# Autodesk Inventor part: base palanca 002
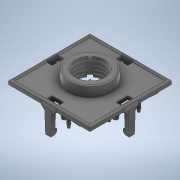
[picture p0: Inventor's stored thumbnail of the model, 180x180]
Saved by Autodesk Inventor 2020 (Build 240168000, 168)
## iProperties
Created: 2022-02
Part Number: base palanca 002
Material: Plástico ABS
Document SubType Name: Modeling
Designer: Eresthor
Density: 1.06 g/cm^3
Appearance: Suave - Negro
Author: Eresthor
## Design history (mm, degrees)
sketch "Boceto1"
  geometry: L1 (-13, 0)-(-18, 0); L2 (-18, 0)-(-18, 11); L3 (0, 12)-(0, 0); L4 (-17, 12)-(-13, 12); L5 (-13, 12)-(-13, 9.25); L6 (-13, 8.25)-(-13, 5.5); L7 (-13, 4.5)-(-13, 2.75); L8 (-13, 1.75)-(-13, 0); A1 r 0.5 centre (-13, 8.75) between (-13, 8.25) and (-13, 9.25); A2 r 0.5 centre (-13, 5) between (-13, 4.5) and (-13, 5.5); A3 r 0.5 centre (-13, 2.25) between (-13, 1.75) and (-13, 2.75); A4 r 1 centre (-17, 11) between (-17, 12) and (-18, 11)
  constraints: 16 end point, 8 point on circle, 4 centre point, 4 perpendicular, 2 horizontal, 2 tangent, 1 vertical
revolve "Revolución1" sketch "Boceto1" stored, may be unused: angle "d11" = 90 deg
sketch "Boceto2"
  geometry: L1 (-6, -36)-(6, -36); L2 (36, -6)-(36, 6); L3 (6, 36)-(-6, 36); L4 (-36, 6)-(-36, -6); L5 (-35, -6)-(-36, -6); L6 (-35, 6)-(-36, 6); L7 (36, -6)-(35, -6); L8 (36, 6)-(35, 6); L9 (6, -36)-(6, -35); L10 (-6, -36)-(-6, -35); L11 (35, 35)-(35, 6); L12 (35, -6)-(35, -35); L13 (-35, 35)-(-6, 35); L14 (6, 35)-(35, 35); L15 (35, -35)-(6, -35); L16 (-6, -35)-(-35, -35); L17 (-35, -35)-(-35, -6); L18 (-35, 6)-(-35, 35); L19 (-6, 35)-(-6, 36); L20 (6, 35)-(6, 36); C1 r 18 at (0, 0)
  constraints: 40 end point, 10 parallel, 5 perpendicular, 2 horizontal, 1 centre point
  dimensions: "d12" = 70 distance of L13.start L11.start; "d13" = 70 distance of L16.end L13.start
extrude "Extrusión1" join sketch "Boceto2" distance "d19" = 3; taper "d20" = 0 deg
feature "Cara para el ángulo de desmoldeo1" dims angle "d21" = 18.43 deg
feature "Cara para el ángulo de desmoldeo2" dims angle "d22" = 45 deg
feature "Cara para el ángulo de desmoldeo3" dims angle "d23" = 45 deg
feature "Cara para el ángulo de desmoldeo4" dims angle "d24" = 45 deg
feature "Cara para el ángulo de desmoldeo5" dims angle "d25" = 45 deg
sketch "Boceto3"
  geometry: L1 (35, -35)-(35, -6) reference; L2 (-35, 35)-(35, 35); L3 (35, 35)-(35, -35); L4 (35, -35)-(-35, -35); L5 (-35, -35)-(-35, 35); L6 (-35, 35)-(35, -35); L7 (35, 35)-(-35, -35); L8 (-32, 32)-(32, 32); L9 (32, 32)-(32, -32); L10 (32, -32)-(-32, -32); L11 (-32, -32)-(-32, 32); L12 (-32, 32)-(32, -32); L13 (32, 32)-(-32, -32); 2 further points
  constraints: 24 end point, 4 midpoint, 4 parallel, 2 horizontal, 2 perpendicular
  dimensions: "d26" = 64 distance of L9.end L10.end; "d27" = 64 distance of L8.end L9.end
extrude "Extrusión2" join sketch "Boceto3" distance "d28" = 1; taper "d29" = 0 deg
fillet "Empalme1" dims "d30" = 1
fillet "Empalme2" dims "d31" = 1.5
sketch "Boceto5"
  geometry: L1 (-7.778, 7.778)-(-8.072, 10.19); L2 (-7.778, 7.778)-(-10.19, 8.072); L3 (7.778, -7.778)-(8.072, -10.19); L4 (7.778, -7.778)-(10.19, -8.072); A1 r 13 centre (0, 0) between (-8.072, 10.19) and (-10.19, 8.072) reference; A2 r 13 centre (0, 0) between (-8.072, 10.19) and (-10.19, 8.072); A3 r 13 centre (0, 0) between (8.072, -10.19) and (10.19, -8.072)
  constraints: 8 end point, 5 point on circle, 2 centre point
extrude "Extrusión4" join sketch "Boceto5" distance "d46" = 4; taper "d47" = 0 deg
sketch "Boceto6"
  geometry: L1 (68.5, 68.5)-(1.5, 68.5) reference; L2 (41, 0)-(29, 0) reference; L3 (69.914, 41.086)-(69.914, 28.914) reference; L4 (0, 29)-(0, 41) reference; L5 (40, 67.5)-(30, 67.5); L6 (2.5, 40)-(2.5, 30); L7 (30, 2.5)-(40, 2.5); L8 (67.5, 30)-(67.5, 40); L9 (40, 7.5)-(30, 7.5); L10 (7.5, 30)-(7.5, 40); L11 (30, 62.5)-(40, 62.5); L12 (62.5, 40)-(62.5, 30); L13 (40, 7.5)-(40, 2.5); L14 (30, 7.5)-(30, 2.5); L15 (7.5, 30)-(2.5, 30); L16 (7.5, 40)-(2.5, 40); L17 (30, 67.5)-(30, 62.5); L18 (40, 67.5)-(40, 62.5); L19 (67.5, 40)-(62.5, 40); L20 (67.5, 30)-(62.5, 30); 1 further point
  constraints: 32 end point, 4 parallel, 2 perpendicular, 1 horizontal
extrude "Extrusión5" cut sketch "Boceto6" distance "d55" = 4; taper "d56" = 0 deg
sketch "Boceto7"
  geometry: L1 (42, 0)-(70, 0) reference; L2 (70, 0)-(70, 28) reference; L3 (68.531, 9.872)-(67.391, 25.831); L4 (40.603, 7.877)-(39.61, 21.781); L5 (68.531, 9.872)-(40.603, 7.877); L6 (67.391, 25.831)-(43.847, 24.15); L7 (60.128, 68.531)-(62.123, 40.603); L8 (60.128, 68.531)-(44.169, 67.391); L9 (44.169, 67.391)-(45.85, 43.847); L10 (62.123, 40.603)-(48.219, 39.61); L11 (1.469, 60.128)-(29.397, 62.123); L12 (1.469, 60.128)-(2.609, 44.169); L13 (2.609, 44.169)-(26.153, 45.85); L14 (29.397, 62.123)-(30.39, 48.219); L15 (9.872, 1.469)-(7.877, 29.397); L16 (9.872, 1.469)-(25.831, 2.609); L17 (25.831, 2.609)-(24.15, 26.153); L18 (7.877, 29.397)-(21.781, 30.39); C1 r 11 at (35, 35); C2 r 1.5 at (64.196, 23.176); C3 r 1.5 at (43.798, 10.534); C4 r 1.5 at (59.466, 43.798); C5 r 1.5 at (46.824, 64.196); C6 r 1.5 at (26.202, 59.466); C7 r 1.5 at (5.804, 46.824); C8 r 1.5 at (10.534, 26.202); C9 r 1.5 at (23.176, 5.804); A1 r 14 centre (35, 35) between (24.15, 26.153) and (39.61, 21.781); A2 r 14 centre (35, 35) between (26.153, 45.85) and (21.781, 30.39); A3 r 14 centre (35, 35) between (43.847, 24.15) and (48.219, 39.61); A4 r 14 centre (35, 35) between (45.85, 43.847) and (30.39, 48.219); 2 further points
  constraints: 32 end point, 13 centre point, 8 point on circle, 1 parallel, 53 other
  dimensions: "d118" = 360 deg dimension on point (35, 35) L3.start (derived)
extrude "Extrusión6" join sketch "Boceto7" distance "d120" = 2; taper "d121" = 0 deg
sketch "Boceto8"
  geometry: L1 (45.855, 43.026)-(44.063, 41.234); L2 (28.766, 25.937)-(26.974, 24.145); L3 (43.026, 45.855)-(41.234, 44.063); L4 (25.937, 28.766)-(24.145, 26.974); A1 r 11 centre (35, 35) between (44.063, 41.234) and (41.234, 44.063); A2 r 11 centre (35, 35) between (25.937, 28.766) and (28.766, 25.937); A3 r 13.5 centre (35, 35) between (45.855, 43.026) and (43.026, 45.855); A4 r 13.5 centre (35, 35) between (24.145, 26.974) and (26.974, 24.145); 1 further point
  constraints: 8 end point, 8 point on circle, 4 centre point, 2 coincident
extrude "Extrusión7" cut sketch "Boceto8" distance "d126" = 10; taper "d127" = 0 deg
sketch "Boceto9"
  geometry: L1 (67.5, -12)-(62.5, -12) reference; L2 (64.58, -12)-(67.619, -12); L3 (67, -2)-(62.5, -2) reference; L4 (64.58, -2)-(67.619, -2); L5 (40, -39)-(40, -34.5) reference; L6 (40, -36.58)-(40, -39.619); L7 (30, -34.5)-(30, -39) reference; L8 (30, -36.58)-(30, -39.619); L9 (3, -12)-(7.5, -12) reference; L10 (5.42, -12)-(2.381, -12); L11 (2.5, -2)-(7.5, -2) reference; L12 (5.42, -2)-(2.381, -2); L13 (30, 20.5)-(30, 25.5) reference; L14 (30, 22.58)-(30, 25.619); L15 (40, 25.5)-(40, 20.5) reference; L16 (40, 22.58)-(40, 25.619); L17 (68.5, -40.5)-(70, -42) reference; L18 (28, 28)-(0, 28) reference; L19 (28.833, -42)-(0, -42) reference; L20 (70, 28)-(70, -0.833) reference; L21 (25.831, -39.391)-(24.15, -15.847) reference; L22 (25.552, -35.473)-(25.781, -38.686); L23 (7.877, -12.603)-(9.872, -40.531) reference; L24 (9.453, -34.668)-(9.17, -30.708); L25 (8.921, -27.221)-(8.479, -21.022); L26 (6.527, 2.448)-(3.314, 2.219); L27 (29.397, 20.123)-(1.469, 18.128) reference; L28 (14.779, 19.079)-(20.978, 19.521); L29 (3.887, -40.234)-(9.453, -34.668); L30 (10.629, -29.25)-(1.766, -38.113); L31 (14.874, 15.247)-(4.241, 25.88); L32 (6.527, 2.448)-(3.314, 2.219); L33 (2.609, 2.169)-(26.153, 3.85) reference; L34 (26.153, 3.85)-(22.303, 3.575); L35 (7.332, 18.547)-(11.292, 18.83); L36 (2.12, 23.759)-(12.753, 13.126); L37 (22.303, 3.575)-(24.097, 1.782); L38 (44.395, 21.491)-(44.219, 24.686); L39 (45.85, 1.847)-(44.169, 25.391) reference; L40 (45.85, 1.847)-(45.575, 5.697); L41 (62.123, -1.397)-(60.128, 26.531) reference; L42 (60.83, 16.708)-(60.547, 20.668); L43 (61.079, 13.221)-(61.521, 7.022); L44 (45.575, 5.697)-(43.782, 3.903); L45 (66.113, 26.234)-(60.547, 20.668); L46 (57.247, 13.126)-(59.371, 15.25); L47 (60.83, 16.708)-(68.234, 24.113); L48 (40.603, -34.123)-(68.531, -32.128) reference; L49 (62.668, -32.547)-(58.708, -32.83); L50 (55.221, -33.079)-(49.022, -33.521); L51 (67.391, -16.169)-(43.847, -17.85) reference; L52 (66.686, -16.219)-(63.473, -16.448); L53 (47.697, -17.575)-(43.847, -17.85); L54 (46.729, -20.85)-(47.529, -21.65); L55 (58.708, -32.83)-(65.759, -39.88); L56 (67.88, -37.759)-(62.668, -32.547); L57 (59.371, -29.25)-(57.247, -27.126); L58 (47.697, -17.575)-(45.903, -15.782); C1 r 1.5 at (64.196, -18.824) reference; A1 r 1.5 centre (67.173, 25.173) between (68.234, 24.113) and (66.113, 26.234); A2 r 1.5 centre (2.827, -39.173) between (1.766, -38.113) and (3.887, -40.234); A3 r 14 centre (35, -7) between (26.153, 3.85) and (21.781, -11.61) reference; A4 r 14 centre (35, -7) between (45.903, -15.782) and (43.782, 3.903); A5 r 30 centre (35, -7) between (25.552, -35.473) and (30, -36.58); A6 r 33 centre (35, -7) between (2.381, -12) and (12.75, -31.371); A7 r 33 centre (35, -7) between (25.781, -38.686) and (30, -39.619); A8 r 30 centre (35, -7) between (5.42, -12) and (8.479, -21.022); A9 r 30 centre (35, -7) between (12.753, -27.126) and (14.874, -29.247); A10 r 1.5 centre (66.82, -38.82) between (65.759, -39.88) and (67.88, -37.759); A11 r 1.5 centre (3.18, 24.82) between (4.241, 25.88) and (2.12, 23.759); A12 r 30 centre (35, -7) between (30, 22.58) and (12.753, 13.126); A13 r 30 centre (35, -7) between (6.527, 2.448) and (5.42, -2); A14 r 33 centre (35, -7) between (30, 25.619) and (10.629, 15.25); A15 r 33 centre (35, -7) between (3.314, 2.219) and (2.381, -2); A16 r 30 centre (35, -7) between (44.448, 21.473) and (40, 22.58); A17 r 33 centre (35, -7) between (44.219, 24.686) and (40, 25.619); A18 r 33 centre (35, -7) between (67.619, -2) and (61.079, 13.221); A19 r 33 centre (35, -7) between (59.371, 15.25) and (57.25, 17.371); A20 r 30 centre (35, -7) between (64.58, -2) and (61.521, 7.022); A21 r 30 centre (35, -7) between (40, -36.58) and (49.022, -33.521); A22 r 33 centre (35, -7) between (40, -39.619) and (55.221, -33.079); A23 r 33 centre (35, -7) between (66.686, -16.219) and (67.619, -12); A24 r 30 centre (35, -7) between (55.126, -29.247) and (57.247, -27.126); A25 r 30 centre (35, -7) between (63.473, -16.448) and (64.58, -12); 14 further points
  constraints: 76 end point, 55 point on circle, 45 point on line, 28 tangent, 25 parallel, 24 centre point, 5 collinear, 1 coincident
extrude "Extrusión8" join sketch "Boceto9" distance "d139" = 1.5; taper "d140" = 0 deg
sketch "Boceto10"
  geometry: C1 r 3.5 at (-27.5, -17); C2 r 3.5 at (-5.5, 5); C3 r 3.5 at (-27.5, 27); C4 r 3.5 at (-49.5, 5); C5 r 1 at (-5.5, 5); C6 r 1 at (-49.5, 5); C7 r 1 at (-27.5, 27); C8 r 1 at (-27.5, -17); C9 r 22 at (-27.5, 5); A1 r 11 centre (-27.5, 5) between (-33.734, -4.063) and (-18.437, 11.234) reference; 2 further points
  constraints: 9 centre point, 5 coincident, 9 other
  dimensions: "d145" = 360 deg dimension on point (-27.5, 5) C1.centre (derived); "d147" = 2 diameter of C5; "d148" = 2 diameter of C6; "d149" = 2 diameter of C7; "d150" = 2 diameter of C8; "d356" = 44 diameter of C9
extrude "Extrusión9" join sketch "Boceto10" distance "d151" = 14; taper "d152" = 0 deg
chamfer "Chaflán1" distance "d153" = 1.5; stored, may be unused: second distance "d154" = 2, angle "d155" = 80 deg
chamfer "Chaflán2" distance "d156" = 1.5; stored, may be unused: second distance "d157" = 2, angle "d158" = 80 deg
chamfer "Chaflán3" distance "d159" = 1.5; stored, may be unused: second distance "d160" = 2, angle "d161" = 80 deg
chamfer "Chaflán4" distance "d162" = 1.5; stored, may be unused: second distance "d163" = 2, angle "d164" = 80 deg
sketch "Boceto11"
  geometry: L1 (29, -43)-(41, -43) reference; L2 (40, -39.5)-(30, -39.5) reference; L3 (38, -39.5)-(32, -39.5); L4 (32, -39.5)-(32, -43); L5 (32, -43)-(38, -43); L6 (38, -43)-(38, -39.5); L7 (71, -10)-(71, -4); L8 (67.5, -10)-(71, -10); L9 (67.5, -4)-(67.5, -10); L10 (71, -4)-(67.5, -4); L11 (38, 29)-(32, 29); L12 (38, 25.5)-(38, 29); L13 (32, 25.5)-(38, 25.5); L14 (32, 29)-(32, 25.5); L15 (-1, -4)-(-1, -10); L16 (2.5, -4)-(-1, -4); L17 (2.5, -10)-(2.5, -4); L18 (-1, -10)-(2.5, -10); 5 further points
  constraints: 32 end point, 2 parallel, 1 horizontal, 1 perpendicular, 33 other
  dimensions: "d165" = 6 distance of L5.end L4.end; "d166" = 3.5 distance of L4.end L3.end; "d169" = 360 deg dimension on point (35, -7) L4.end (derived)
extrude "Extrusión10" join sketch "Boceto11" distance "d171" = 16; taper "d172" = 0 deg
sketch "Boceto12"
  geometry: L1 (32, -43)-(38, -43) reference; L2 (38, -43)-(32, -43); L3 (32, -43)-(32, -38); L4 (32, -38)-(38, -38); L5 (38, -38)-(38, -43); L6 (71, -10)-(66, -10); L7 (71, -4)-(71, -10); L8 (66, -4)-(71, -4); L9 (66, -10)-(66, -4); L10 (38, 29)-(38, 24); L11 (32, 29)-(38, 29); L12 (32, 24)-(32, 29); L13 (38, 24)-(32, 24); L14 (-1, -4)-(4, -4); L15 (-1, -10)-(-1, -4); L16 (4, -10)-(-1, -10); L17 (4, -4)-(4, -10); 2 further points
  constraints: 32 end point, 2 parallel, 1 horizontal, 1 perpendicular, 33 other
  dimensions: "d173" = 6 distance of L3.end L4.end; "d174" = 5 distance of L2.end L3.end; "d177" = 360 deg dimension on point (35, -7) L2.end (derived)
extrude "Extrusión11" join sketch "Boceto12" distance "d179" = 4; taper "d180" = 0 deg
chamfer "Chaflán5" distance "d181" = 1.5; stored, may be unused: second distance "d182" = 2, angle "d183" = 80 deg
feature "Cara para el ángulo de desmoldeo6" dims angle "d184" = 2 deg
feature "Cara para el ángulo de desmoldeo7" dims angle "d185" = 2 deg
feature "Cara para el ángulo de desmoldeo8" dims angle "d186" = 2 deg
feature "Cara para el ángulo de desmoldeo9" dims angle "d187" = 2 deg
node "Plano de trabajo1"
node "Plano de trabajo2"
node "Plano de trabajo3"
node "Plano de trabajo4"
sketch "Boceto13"
  geometry: L1 (7.61, 0)-(-5.782, 0) reference; L2 (6, 0)-(5.302, -20) reference; L3 (5.895, -2.998)-(9, 0); L4 (9.234, 0)-(-8, 0) reference; L5 (-2.98, 0)-(0.105, -2.999); L6 (0, 0)-(0.698, -20) reference; 2 further points
  constraints: 4 end point, 4 point on line
feature "Nervio1" sketch "Boceto13" dims "d194" = 1, "d195" = 3, "d196" = 0, "d197" = 0, "d198" = 1, "d199" = 1
sketch "Boceto14"
  geometry: L1 (0, 0)-(0.698, -20) reference; L2 (0.105, -2.998)-(-3, 0); L3 (-2, 0)-(-6.219, 0) reference; 1 further point
  constraints: 2 end point, 2 point on line
feature "Nervio2" sketch "Boceto14" dims "d201" = 1, "d202" = 3, "d203" = 0, "d204" = 0, "d205" = 1, "d206" = 1
sketch "Boceto15"
  geometry: L1 (6, 0)-(5.441, -16) reference; L2 (0, 0)-(0.559, -16) reference; L3 (9, 0)-(9, 3) reference; L4 (9, 0)-(5.895, -2.998); L5 (14, 0)-(-3.234, 0) reference; 2 further points
  constraints: 2 end point, 1 point on line
feature "Nervio3" sketch "Boceto15" dims "d209" = 1, "d210" = 3, "d211" = 0, "d212" = 0, "d213" = 1, "d214" = 1
sketch "Boceto16"
  geometry: 1 further point
sketch "Boceto17"
  geometry: L1 (0, 0)-(0.559, -16) reference; L2 (14, 0)-(-3.234, 0) reference; L3 (-3, 0)-(0.105, -2.998); 2 further points
  constraints: 2 end point, 2 point on line
feature "Nervio4" sketch "Boceto17" dims "d216" = 1, "d217" = 3, "d218" = 0, "d219" = 0, "d220" = 1, "d221" = 1
sketch "Boceto18"
  geometry: L1 (6, 0)-(5.302, -20) reference; L2 (10.669, 0)-(-10, 0) reference; L3 (9, 0)-(5.895, -2.998); 2 further points
  constraints: 2 end point, 2 point on line
feature "Nervio5" sketch "Boceto18" dims "d223" = 1, "d224" = 3, "d225" = 0, "d226" = 0, "d227" = 1, "d228" = 1
sketch "Boceto19"
  geometry: L1 (-2, 0)-(0, 0) reference; L2 (-3, 0)-(0.105, -2.998); L3 (0, 0)-(0.698, -20) reference; 1 further point
  constraints: 2 end point, 1 point on line
feature "Nervio6" sketch "Boceto19" dims "d230" = 1, "d231" = 3, "d232" = 0, "d233" = 0, "d234" = 1, "d235" = 1
sketch "Boceto20"
  geometry: L1 (6, 0)-(5.441, -16) reference; L2 (10.669, 0)-(-10, 0) reference; L3 (9, 0)-(5.895, -2.998); 2 further points
  constraints: 2 end point, 2 point on line
feature "Nervio7" sketch "Boceto20" dims "d237" = 1, "d238" = 3, "d239" = 0, "d240" = 0, "d241" = 1, "d242" = 1
sketch "Boceto21"
  geometry: L1 (0, 0)-(0.559, -16) reference; L2 (-11.022, 0)-(-2.603, 0) reference; L3 (-3, 0)-(0.105, -2.998); 1 further point
  constraints: 2 end point, 2 point on line
feature "Nervio8" sketch "Boceto21" dims "d244" = 1, "d245" = 3, "d246" = 0, "d247" = 0, "d248" = 1, "d249" = 1
sketch "Boceto22"
  geometry: C1 r 1.5 at (0, 0) reference; C2 r 1.5 at (0, 0); C3 r 1.5 at (-20.399, -12.642) reference; C4 r 1.5 at (-20.399, -12.642); C5 r 1.5 at (-41.021, -17.372) reference; C6 r 1.5 at (-41.021, -17.372); C7 r 1.5 at (-53.663, 3.027) reference; C8 r 1.5 at (-53.663, 3.027); C9 r 1.5 at (-58.393, 23.649) reference; C10 r 1.5 at (-58.393, 23.649); C11 r 1.5 at (-37.994, 36.291) reference; C12 r 1.5 at (-37.994, 36.291); C13 r 1.5 at (-17.372, 41.021) reference; C14 r 1.5 at (-17.372, 41.021); C15 r 1.5 at (-4.73, 20.622) reference; C16 r 1.5 at (-4.73, 20.622); 1 further point
  constraints: 8 centre point, 8 coincident
extrude "Extrusión12" join sketch "Boceto22" distance "d250" = 2; taper "d251" = 0 deg
sketch "Boceto25"
  geometry: C1 r 1.5 at (4.924, 46.84); C2 r 1.5 at (27.082, 59.451); C3 r 1.5 at (10.549, 27.082); C4 r 1.5 at (23.16, 4.924); C5 r 1.5 at (42.918, 10.549); C6 r 1.5 at (65.076, 23.16); C7 r 1.5 at (59.451, 42.918); C8 r 1.5 at (46.84, 65.076); 2 further points
  constraints: 8 centre point, 17 other
  dimensions: "d328" = 360 deg dimension on point (35, 35) C2.centre (derived)
extrude "Extrusión15" join sketch "Boceto25" distance "d330" = 9; taper "d331" = 0 deg
chamfer "Chaflán22" distance "d332" = 0.5; stored, may be unused: second distance "d333" = 3, angle "d334" = 45 deg
chamfer "Chaflán23" distance "d335" = 0.5; stored, may be unused: second distance "d336" = 3, angle "d337" = 45 deg
chamfer "Chaflán24" distance "d338" = 0.5; stored, may be unused: second distance "d339" = 3, angle "d340" = 45 deg
chamfer "Chaflán25" distance "d341" = 0.5; stored, may be unused: second distance "d342" = 3, angle "d343" = 45 deg
chamfer "Chaflán26" distance "d344" = 0.5; stored, may be unused: second distance "d345" = 3, angle "d346" = 45 deg
chamfer "Chaflán27" distance "d347" = 0.5; stored, may be unused: second distance "d348" = 3, angle "d349" = 45 deg
chamfer "Chaflán28" distance "d350" = 0.5; stored, may be unused: second distance "d351" = 3, angle "d352" = 45 deg
chamfer "Chaflán29" distance "d353" = 0.5; stored, may be unused: second distance "d354" = 3, angle "d355" = 45 deg
node "Sólido1"
other parameters: "d14" = 1, "d15" = 6, "d16" = 6, "d17" = 6, "d18" = 6, "d36" = 26, "d188" = -1.75, "d189" = -1.75, "d190" = -1.75, "d191" = -1.75
